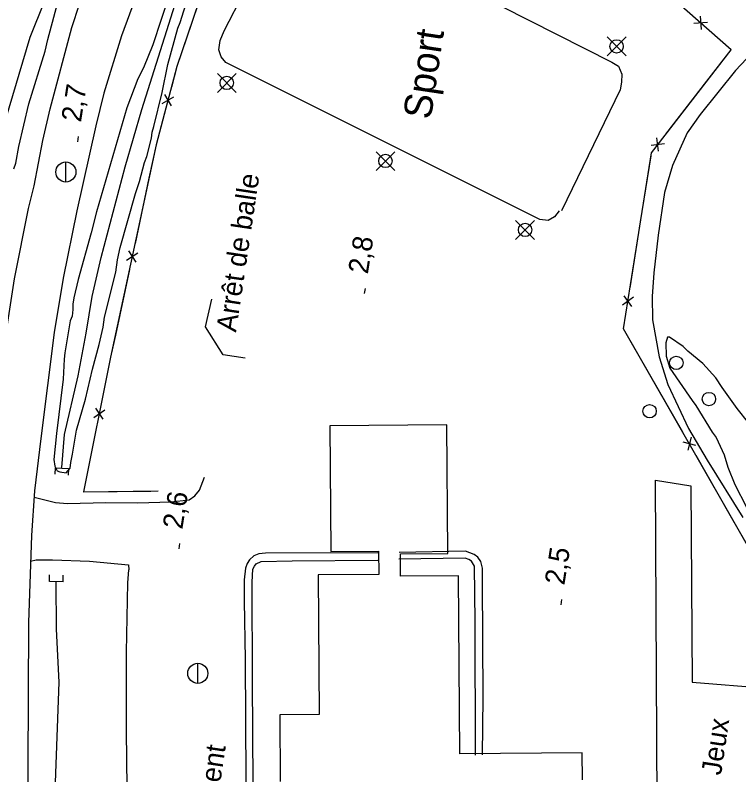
# Model space of a CAD drawing. Extents: x 282461 to 284471, y 5554090 to 5557646.
# Drawn here: x 283064.7 to 283172.9, y 5555423.2 to 5555536.8 of the extents above; entities that cross this region are included whole.
import ezdxf

# ---------------------------------------------------------------- set-up
doc = ezdxf.new("R2010")
doc.units = 0
for name, color, linetype in [('Niveau 19', 7, 'Continuous'), ('Niveau 2', 7, 'Continuous'), ('Niveau 21', 7, 'Continuous'), ('Niveau 22', 7, 'Continuous'), ('Niveau 26', 7, 'Continuous'), ('Niveau 3', 7, 'Continuous'), ('Niveau 31', 7, 'Continuous'), ('Niveau 36', 7, 'Continuous'), ('Niveau 37', 7, 'Continuous'), ('Niveau 4', 7, 'Continuous'), ('Niveau 52', 7, 'Continuous'), ('Niveau 56', 7, 'Continuous')]:
    doc.layers.add(name, color=color, linetype=linetype)

msp = doc.modelspace()

# ---------------------------------------------------------------- linework, layer by layer
at = {"layer": 'Niveau 19'}
for points in [[(283067.5, 5555464.74), (283070.71, 5555463.99), (283072.46, 5555463.84), (283078.2, 5555463.96), (283083.01, 5555463.9), (283087.94, 5555464.08), (283090.68, 5555464.35), (283091.54, 5555464.94), (283092.22, 5555465.82), (283092.95, 5555467.74)], [(283066.96, 5555455.21), (283067.82, 5555455.38), (283070.24, 5555455.4), (283075.75, 5555455.17), (283081.62, 5555454.66), (283081.63, 5555453.91)]]:
    msp.add_lwpolyline(points, dxfattribs=at)
at = {"layer": 'Niveau 2'}
for points in [[(283064.48, 5555513.86), (283064.76, 5555514.73), (283065.19, 5555517.18), (283066.68, 5555523.58), (283069.14, 5555531.45), (283069.52, 5555533.2), (283072.25, 5555543.27), (283072.63, 5555545.13), (283072.45, 5555545.71), (283071.47, 5555544.95), (283070.22, 5555542.49), (283069.67, 5555540.69), (283068.99, 5555538.82), (283066.85, 5555533.51), (283063.17, 5555521.1)], [(283087.72, 5555540.03), (283085.26, 5555532.4), (283083.85, 5555528.95), (283083, 5555527.32), (283081.37, 5555523), (283076.8, 5555507.45), (283076.03, 5555504.3), (283074.08, 5555497.31), (283073.42, 5555494.58), (283073.26, 5555493.64), (283073.27, 5555492.83), (283073.16, 5555491.84), (283072.88, 5555491.14), (283072.07, 5555486.37), (283071.96, 5555485.39), (283071.83, 5555482.42), (283070.82, 5555474.28), (283070.46, 5555470.39), (283070.59, 5555469.41), (283070.95, 5555468.71), (283071.36, 5555468.54), (283072.29, 5555468.38), (283072.86, 5555469.08), (283072.96, 5555469.96)], [(283072.96, 5555469.96), (283073.24, 5555471.18), (283073.83, 5555474.78), (283075.17, 5555479.44), (283076.22, 5555483.93), (283077.22, 5555487.59), (283077.82, 5555490.21), (283078.04, 5555491.67), (283079.7, 5555498.42), (283079.96, 5555500.28), (283080.35, 5555502.09), (283082.63, 5555510.18), (283083.25, 5555511.99), (283084.02, 5555514.79), (283084.36, 5555515.72), (283085.03, 5555518.46), (283085.13, 5555519.33), (283085.41, 5555520.2), (283086.63, 5555525.27), (283087.5, 5555529.46), (283089, 5555534.88), (283089.34, 5555535.75), (283090.74, 5555540.24)], [(283174.39, 5555475.84), (283172.63, 5555478.03), (283170.38, 5555481.14), (283169.44, 5555482.63), (283167.5, 5555484.76), (283165.27, 5555486.59), (283164.56, 5555487.28), (283162.52, 5555488.71), (283162.23, 5555488.7), (283161.95, 5555487.83), (283162.03, 5555485.86), (283162.57, 5555484.06), (283165.88, 5555479.23), (283166.47, 5555478.48), (283168.9, 5555474.5), (283169.49, 5555473.7), (283170.68, 5555471.1), (283171.22, 5555469.25), (283172.3, 5555466.65), (283174.02, 5555463.25)]]:
    msp.add_lwpolyline(points, dxfattribs=at)
at = {"layer": 'Niveau 21'}
for points in [[(283066.66, 5555507.93), (283067.48, 5555511.31), (283068.79, 5555518.11), (283069.9, 5555522.83), (283073.13, 5555535), (283075.43, 5555542.05), (283076.27, 5555544.32), (283077.83, 5555549.62), (283086.71, 5555574.85), (283091.57, 5555587.49), (283097.52, 5555603.69), (283105.48, 5555627.33)], [(283082.6, 5555539.35), (283080.58, 5555533.75), (283077.94, 5555525.19), (283076.73, 5555520.3), (283073.86, 5555507.56), (283071.84, 5555497.5), (283070.48, 5555489.41), (283068.47, 5555473.55), (283067.57, 5555465.71), (283067.08, 5555459.03), (283066.65, 5555446.03), (283066.43, 5555402.69)], [(283059.96, 5555174.63), (283060.09, 5555177.87), (283060.21, 5555186.07), (283060.12, 5555201.45), (283060.36, 5555210.73), (283060.14, 5555228.29), (283060.53, 5555244.18), (283060.56, 5555263.98), (283060.77, 5555271.18), (283060.27, 5555303.27), (283060.09, 5555324.29), (283060.11, 5555345.02), (283059.8, 5555365.9), (283059.95, 5555377.73), (283060.17, 5555387.77), (283059.98, 5555399.2), (283059.86, 5555427.39), (283060.45, 5555446.02), (283060.43, 5555452.22), (283060.56, 5555460.58), (283061.88, 5555476.37), (283063.34, 5555489.62), (283064.58, 5555497.41), (283066.66, 5555507.93)]]:
    msp.add_lwpolyline(points, dxfattribs=at)
at = {"layer": 'Niveau 22'}
for points in [[(283178.18, 5555534.7), (283172.36, 5555528.57), (283167.09, 5555522), (283165.15, 5555519.25), (283162.95, 5555514.35), (283161.78, 5555510.33), (283160.81, 5555503.94), (283160.19, 5555498.3), (283159.94, 5555494.75), (283159.98, 5555491.27), (283160.98, 5555485.77), (283162.24, 5555481.6), (283165.35, 5555475.03), (283168.13, 5555470.31), (283173.46, 5555461.73)], [(283118.9, 5555456.44), (283102.1, 5555456.38), (283101.12, 5555456.28), (283100.34, 5555455.98), (283099.71, 5555455.39), (283099.34, 5555454.86), (283099.11, 5555454.14), (283098.9, 5555452.42), (283098.91, 5555449.26), (283099.05, 5555440.5), (283099.36, 5555386.62), (283099.48, 5555376.76), (283099.64, 5555372.52), (283100.09, 5555371.49), (283102.45, 5555368.58), (283108.76, 5555360.35), (283109.44, 5555359.69), (283109.76, 5555359.61), (283111.44, 5555359.54), (283125.24, 5555359.84), (283143.52, 5555359.93), (283143.48, 5555365.09)], [(283134.56, 5555426.21), (283134.63, 5555434.74), (283134.56, 5555452.15), (283134.54, 5555454.15), (283134.32, 5555455.16), (283133.85, 5555455.8), (283133.3, 5555456.2), (283132.01, 5555456.7), (283122.07, 5555456.47)], [(283100.37, 5555406.39), (283100.14, 5555437.28), (283100.12, 5555452.06), (283100.22, 5555453.98), (283100.44, 5555454.47), (283100.7, 5555454.79), (283101.44, 5555455.12), (283106.06, 5555455.26), (283118.88, 5555455.35)], [(283133.48, 5555426.2), (283133.45, 5555446.16), (283133.35, 5555454.43), (283132.9, 5555455.18), (283132.52, 5555455.43), (283131.97, 5555455.63), (283122.05, 5555455.51)]]:
    msp.add_lwpolyline(points, dxfattribs=at)
at = {"layer": 'Niveau 26'}
for p, q in [((283070.64, 5555469.17), (283070.58, 5555468.18)), ((283070.64, 5555469.17), (283072.65, 5555469.06)), ((283072.65, 5555469.06), (283072.59, 5555468.06)), ((283069.79, 5555452.13), (283069.8, 5555453.13)), ((283071.82, 5555452.11), (283071.81, 5555453.12)), ((283071.82, 5555452.11), (283069.79, 5555452.13))]:
    msp.add_line(p, q, dxfattribs=at)
at = {"layer": 'Niveau 3'}
for p, q in [((283074.01, 5555517.91), (283074.13, 5555518.7)), ((283116.91, 5555495.2), (283117.03, 5555495.99)), ((283089.17, 5555457.03), (283089.29, 5555457.82)), ((283146.3, 5555448.68), (283146.42, 5555449.47))]:
    msp.add_line(p, q, dxfattribs=at)
at = {"layer": 'Niveau 31'}
msp.add_lwpolyline([(283149.49, 5555422.5), (283149.45, 5555426.54), (283131.17, 5555426.39), (283130.96, 5555453.01), (283122.3, 5555452.94), (283122.28, 5555456.31), (283129.36, 5555456.36), (283129.2, 5555475.58), (283111.72, 5555475.44), (283111.87, 5555456.62), (283119.01, 5555456.68), (283119.04, 5555453.22), (283109.97, 5555453.15), (283110.14, 5555432.26), (283104.22, 5555432.21), (283104.29, 5555422.25)], dxfattribs=at)
at = {"layer": 'Niveau 36'}
for p, q in [((283156.01, 5555530.76), (283153.19, 5555533.58)), ((283153.19, 5555530.76), (283156.01, 5555533.58)), ((283097.71, 5555525.29), (283094.89, 5555528.11)), ((283094.89, 5555525.29), (283097.71, 5555528.11)), ((283121.44, 5555513.61), (283118.62, 5555516.43)), ((283118.62, 5555513.61), (283121.44, 5555516.43)), ((283072.23, 5555511.88), (283072.23, 5555514.88)), ((283142.32, 5555503.3), (283139.5, 5555506.12)), ((283139.5, 5555503.3), (283142.32, 5555506.12)), ((283091.96, 5555436.92), (283091.96, 5555439.92))]:
    msp.add_line(p, q, dxfattribs=at)
for centre, radius in [((283154.6, 5555532.18), 1), ((283096.3, 5555526.71), 1), ((283120.03, 5555515.04), 1), ((283072.24, 5555513.39), 1.5), ((283140.92, 5555504.73), 1), ((283163.53, 5555484.84), 1), ((283168.41, 5555479.44), 1), ((283159.54, 5555477.62), 1), ((283091.97, 5555438.42), 1.5)]:
    msp.add_circle(centre, radius, dxfattribs=at)
at = {"layer": 'Niveau 37'}
for p, q in [((283167.11, 5555536.68), (283167.23, 5555534.68)), ((283168.17, 5555535.74), (283166.17, 5555535.62)), ((283086.64, 5555523.63), (283088.37, 5555524.64)), ((283087, 5555525), (283088.01, 5555523.27)), ((283160.89, 5555516.49), (283160.63, 5555518.48)), ((283161.75, 5555517.61), (283159.77, 5555517.36)), ((283081.32, 5555500.2), (283083, 5555501.29)), ((283081.61, 5555501.59), (283082.7, 5555499.9)), ((283157.11, 5555494.67), (283155.49, 5555493.49)), ((283156.89, 5555493.27), (283155.72, 5555494.89)), ((283076.68, 5555478.09), (283077.79, 5555476.42)), ((283076.4, 5555476.7), (283078.07, 5555477.81)), ((283165.76, 5555473.72), (283165.23, 5555471.78)), ((283166.46, 5555472.49), (283164.53, 5555473.01))]:
    msp.add_line(p, q, dxfattribs=at)
for points in [[(283100.78, 5555369.89), (283100.57, 5555369.89), (283100.63, 5555346.28), (283173.73, 5555346.94), (283201.81, 5555359.78), (283219.05, 5555360.37), (283220.76, 5555366.73), (283218.89, 5555402.92), (283208.11, 5555416.06), (283175.14, 5555455.89), (283155.65, 5555489.95), (283159.82, 5555516.27), (283171.73, 5555531.64), (283156.94, 5555544.74), (283147.78, 5555551.39), (283136.32, 5555556.46), (283123.09, 5555561.58), (283102.03, 5555568.05), (283088.84, 5555529.18), (283085.74, 5555517.46), (283078.93, 5555485.69), (283074.88, 5555465.54), (283086.05, 5555465.69)], [(283146.02, 5555507.6), (283145.3, 5555506.69), (283144.36, 5555506.13), (283143.13, 5555506.28), (283096.15, 5555529.77), (283095.46, 5555530.62), (283095.09, 5555531.68), (283095.32, 5555533.06), (283095.89, 5555534.5), (283105.03, 5555552.18), (283105.83, 5555552.9), (283107.23, 5555553.11), (283108.67, 5555552.74), (283153.88, 5555529.83), (283154.9, 5555529.23), (283155.36, 5555528.03), (283155.34, 5555526.82), (283155.11, 5555525.67), (283146.34, 5555507.59)], [(283094.23, 5555545.07), (283091.02, 5555535.6)], [(283091.02, 5555535.6), (283088.84, 5555529.18), (283088.02, 5555526.07)], [(283168.11, 5555526.97), (283171.73, 5555531.64), (283168.67, 5555534.35)], [(283161.98, 5555519.06), (283168.11, 5555526.97)], [(283086.99, 5555522.2), (283085.74, 5555517.46), (283084.67, 5555512.48)], [(283158.18, 5555505.93), (283159.75, 5555515.81)], [(283084.67, 5555512.48), (283082.58, 5555502.7)], [(283156.62, 5555496.06), (283158.18, 5555505.93)], [(283081.74, 5555498.79), (283079.64, 5555489.01)], [(283159.53, 5555483.16), (283155.65, 5555489.95), (283155.99, 5555492.11)], [(283079.64, 5555489.01), (283078.93, 5555485.69), (283077.63, 5555479.22)], [(283164.5, 5555474.49), (283159.53, 5555483.16)], [(283076.84, 5555475.3), (283074.88, 5555465.54), (283074.93, 5555465.54)], [(283171.45, 5555462.33), (283166.49, 5555471.01)], [(283074.93, 5555465.54), (283084.93, 5555465.67)], [(283176.78, 5555453.91), (283175.14, 5555455.89), (283171.45, 5555462.33)]]:
    msp.add_lwpolyline(points, dxfattribs=at)
at = {"layer": 'Niveau 4'}
for points in [[(283071.62, 5555469.18), (283072.03, 5555474.12), (283074.07, 5555482.91), (283075.26, 5555489.3), (283076.18, 5555494.77), (283077.54, 5555500.59), (283081.09, 5555514.16), (283083.6, 5555522.73), (283089.19, 5555540.45)], [(283070.76, 5555376.49), (283071.03, 5555393.29), (283070.7, 5555422.1), (283071.23, 5555437.09), (283070.84, 5555445.04), (283070.81, 5555452.12)]]:
    msp.add_lwpolyline(points, dxfattribs=at)
at = {"layer": 'Niveau 52'}
msp.add_lwpolyline([(283080.95, 5555371.34), (283081.1, 5555372.61), (283081.27, 5555382.65), (283081.98, 5555406.52), (283086.39, 5555406.8), (283086.61, 5555407.62), (283086.54, 5555408.43), (283086.39, 5555420.96), (283086.33, 5555421.19), (283081.4, 5555421.31), (283081.29, 5555429.78), (283081.32, 5555441.61), (283081.53, 5555451.93), (283081.63, 5555453.91)], dxfattribs=at)
at = {"layer": 'Niveau 56'}
for points in [[(283099.06, 5555485.53), (283095.78, 5555486.04), (283093.11, 5555490.23), (283094.06, 5555494.36)], [(283181.75, 5555402.59), (283164.89, 5555402.78), (283165.3, 5555418.4), (283160.65, 5555419.01), (283160.43, 5555467.29), (283165.71, 5555466.46), (283165.9, 5555437.08), (283177.02, 5555436.21), (283176.86, 5555422.67), (283181.61, 5555422.47), (283181.75, 5555402.59)]]:
    msp.add_lwpolyline(points, dxfattribs=at)

# ---------------------------------------------------------------- texts
at = {"layer": 'Niveau 3'}
for s, p in [('2,7  ', (283074.49, 5555520.75)), ('2,8  ', (283117.39, 5555498.04)), ('2,6  ', (283089.65, 5555459.87)), ('2,5  ', (283146.78, 5555451.52))]:
    msp.add_text(s, height=3, rotation=81.0957, dxfattribs=at).set_placement(p)
at = {"layer": 'Niveau 52'}
msp.add_text('Stationnement', height=2.9999, rotation=81.5139, dxfattribs=at).set_placement((283092.34, 5555401.92))
at = {"layer": 'Niveau 56'}
for s, height, p in [('Sport', 4.2, (283126.81, 5555521.13)), ('Arrêt de balle', 2.9999, (283097.68, 5555489.35)), ('Jeux', 3, (283170.21, 5555423.08))]:
    msp.add_text(s, height=height, rotation=81.5139, dxfattribs=at).set_placement(p)

doc.saveas('drawing.dxf')
